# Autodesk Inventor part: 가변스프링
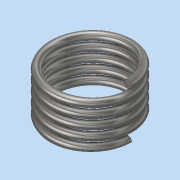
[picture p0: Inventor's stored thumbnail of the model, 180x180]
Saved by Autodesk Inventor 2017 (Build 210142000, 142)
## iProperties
Part Number: 가변스프링
Material: 스테인레스 스틸
Document SubType Name: Modeling
Designer: mrc
Mass: 7.77588 g
Surface Area: 19.7122 cm^2
Volume: 0.971985 cm^3
Density: 8 g/cm^3
Appearance: 반연마
Author: mrc
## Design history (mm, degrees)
sketch "스케치1"
  geometry: L1 (0, 0)-(10, 0); L2 (10, 0)-(10, 12.7); L3 (10, 12.7)-(0, 12.7); L4 (0, 12.7)-(0, 0); C1 r 1 at (10, 0)
  constraints: 8 end point, 2 parallel, 1 centre point, 1 coincident, 1 horizontal, 1 perpendicular
  dimensions: "d0" = 2 diameter of C1; "d1" = 20 diameter of L2 L4; "d2" = 12.7 distance between parallel lines of L1 L3 (derived)
feature "코일1" sketch "스케치1" pitch "d3" = 10; turns "d5" = 5; dims "d4" = 12.7 (= d2), "d6" = 0, angle "d7" = 90 deg, angle "d8" = 90 deg, "d9" = 0, "d10" = 0
sketch "스케치2"
  geometry: L1 (-15, 28)-(15, 28); L2 (15, 28)-(15, 0); L3 (15, 0)-(-15, 0); L4 (-15, 0)-(-15, 28); 2 further points
  constraints: 8 end point, 2 parallel, 1 coincident, 1 horizontal, 1 midpoint, 1 perpendicular
  dimensions: "d11" = 28 distance of L1.end L2.end; "d12" = 30 distance of L1.start L1.end
extrude "돌출1" sketch "스케치2" stored distance "d13" = 30; taper "d14" = 0 deg
node "솔리드1"
